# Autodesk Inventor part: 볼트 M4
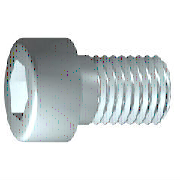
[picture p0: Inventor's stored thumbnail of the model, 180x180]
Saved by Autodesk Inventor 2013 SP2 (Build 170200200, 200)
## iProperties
IsCustomPart: 1
Created: 2015-10
Part Number: 볼트 M4
Material: 강, 연강
Description: 6각머리 태핑 나사
Document SubType Name: Modeling
Standard: KS B 1003
Designer: mdu
Standards Organization: KS
Language: ko-KR
Size Designation: M 4 x 16
Categories: <MemberInstance><Categories><Category DisplayName="조임쇠" InternalName="e4da775c-781d-43d5-af7c-5136215cf5a6" Mnemonic="FSTN"><Category DisplayName="볼트" InternalN
Density: 7.86 g/cm^3
Mass: 2.62973 g
Surface Area: 3.81118 cm^2
Volume: 0.334572 cm^3
Author: mdu
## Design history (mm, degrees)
sketch "스케치1"
  geometry: L1 (-1, 0)-(16, 0); L2 (16, 0)-(16, 2); L3 (16, 2)-(1.75, 2); L4 (1.75, 2)-(1.32, 2); L5 (1.32, 2)-(0, 2); L6 (0, 2)-(0, 3.5); L7 (0, 3.5)-(-4, 3.5); L8 (-4, 3.5)-(-4, 1.732); L9 (-4, 1.732)-(-2, 1.732); L10 (-2, 1.732)-(-1, 0); L11 (-8, 0)-(20, 0) reference; L12 (0, -0.7)-(0, 4.2) reference; L13 (1.75, 2)-(0, 2)
  constraints: 22 end point, 6 parallel, 2 collinear, 2 perpendicular, 1 horizontal, 1 point on line
  dimensions: "d1" = 14.25 distance from line of L3.end L2 (= GEL); "d2" = 0.42952 distance of L4.end L3.end (computed from GAL); "d3" = 4 distance between parallel lines of L8 L6 (= KOH); "d4" = 2 distance of L8.end L9.end (= INTI); "d5" = 60 deg angle of L10 L1; "d6" = 4 diameter of L3 L1 (= GD); "d7" = 4 diameter of L5 L1 (= BDM); "d8" = 3.4641 diameter of L9 L1 (= 1.1547 x SW); "d9" = 7 diameter of L7 L1 (= KOD); "d26" = 16 distance between parallel lines of L12 L2 (= NLG)
revolve "본체" sketch "스케치1" stored, may be unused: angle "d10" = 90 deg
sketch "스케치2"
  geometry: L1 (0, -4.9)-(0, 4.9) reference; L2 (-4.9, 0)-(4.9, 0) reference; L3 (1.732, 0)-(0.866, -1.5); L4 (0.866, -1.5)-(-0.866, -1.5); L5 (-0.866, -1.5)-(-1.732, 0); L6 (-1.732, 0)-(-0.866, 1.5); L7 (-0.866, 1.5)-(0.866, 1.5); L8 (0.866, 1.5)-(1.732, 0); 2 further points
  constraints: 12 end point, 1 coincident, 1 horizontal alignment, 1 point on line, 12 other
extrude "슬롯" join sketch "스케치2" stored distance "d11" = 10; taper "d12" = 0 deg
workplane "Work Plane1"
fillet "Fillet2" dims "d30" = 0.1 (= R)
body "Solid1"
fillet "모깎기1" dims "d17" = 0.4 (= RR)
feature "스레드" dims "d13" = 14.25 (= GEL), "d14" = 0
chamfer "모따기1" distance "d15" = 0.42941 (= -0.5 x SPD + 0.5 x GD); stored, may be unused: second distance "d16" = 0.42941 (= GUL), angle "d27" = 45 deg
other parameters: "GD" = 4 (= NND) [user parameter; used in 2 equation terms], "NLG" = 16 [user parameter; used in 1 equation term], "GEL" = 14.25 [user parameter; used in 2 equation terms], "KOD" = 7 [user parameter; used in 1 equation term], "KOH" = 4 [user parameter; used in 1 equation term], "INTI" = 2 [user parameter; used in 1 equation term], "GAL" = 0.42941 (= 0.61345 x PTC) [user parameter; used in 1 equation term], "GUL" = 0.42941 (= 0.61345 x PTC) [user parameter; used in 1 equation term], "BDM" = 4 (= NND) [user parameter; used in 1 equation term], "SW" = 3 [user parameter; used in 2 equation terms], "RR" = 0.4 [user parameter; used in 1 equation term], "SPD" = 3.14117 (= NND - 1.2269 x PTC) [user parameter; used in 1 equation term], "d19" = 0, "d28" = 0, "d29" = 0, "R" = 0.1 [user parameter; used in 1 equation term], "PHH" = 0.2 [user parameter], "GD1" = 3.14117 (= THREADDIA - 1.2269 x PTC) [user parameter], "THREADDIA" = 4 [user parameter; used in 1 equation term], "FAWI" = 45 deg [user parameter], "TPU" = 14.28571 (computed from PTC) [user parameter], "PTC" = 0.7 [user parameter; used in 5 equation terms], "NND" = 4 [user parameter; used in 3 equation terms], "TOA" = 30 deg [user parameter], "E0" = 3.465 (= 1.155 x SW) [user parameter]
